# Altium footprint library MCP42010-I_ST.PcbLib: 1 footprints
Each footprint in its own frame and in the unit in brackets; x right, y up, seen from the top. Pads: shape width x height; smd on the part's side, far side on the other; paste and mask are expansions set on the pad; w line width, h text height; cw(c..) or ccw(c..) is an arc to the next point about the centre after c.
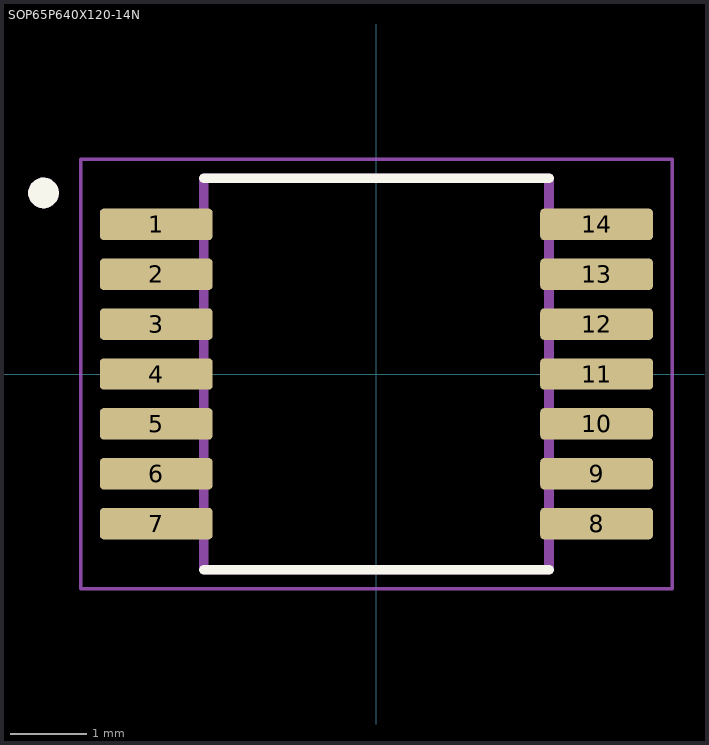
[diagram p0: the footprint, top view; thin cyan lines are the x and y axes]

## SOP65P640X120-14N [mm]
pads (14):
  rrect25% 1.47x0.41 smd: 1(-2.87,1.95) 2(-2.87,1.3) 3(-2.87,0.65) 4(-2.87,0) 5(-2.87,-0.65) 6(-2.87,-1.3) 7(-2.87,-1.95) 8(2.87,-1.95) 9(2.87,-1.3) 10(2.87,-0.65) 11(2.87,0) 12(2.87,0.65) 13(2.87,1.3) 14(2.87,1.95)
Top Overlay:
  circle w0.2: c-4.34,2.36 r0.1
  lines w0.127: -2.25,-2.55 2.25,-2.55 ; -2.25,2.55 2.25,2.55
Mechanical 13:
  circle w0.2: c-4.34,2.36 r0.1
  lines w0.127: -2.25,-2.55 2.25,-2.55 2.25,2.55 -2.25,2.55 -2.25,-2.55
Mechanical 15:
  lines w0.05: -3.855,-2.8 3.855,-2.8 3.855,2.8 -3.855,2.8 -3.855,-2.8
3D body "MCP42010-I_ST.STEP": height 1.2, standoff 0, extent -3.217,-2.491 3.183,2.509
